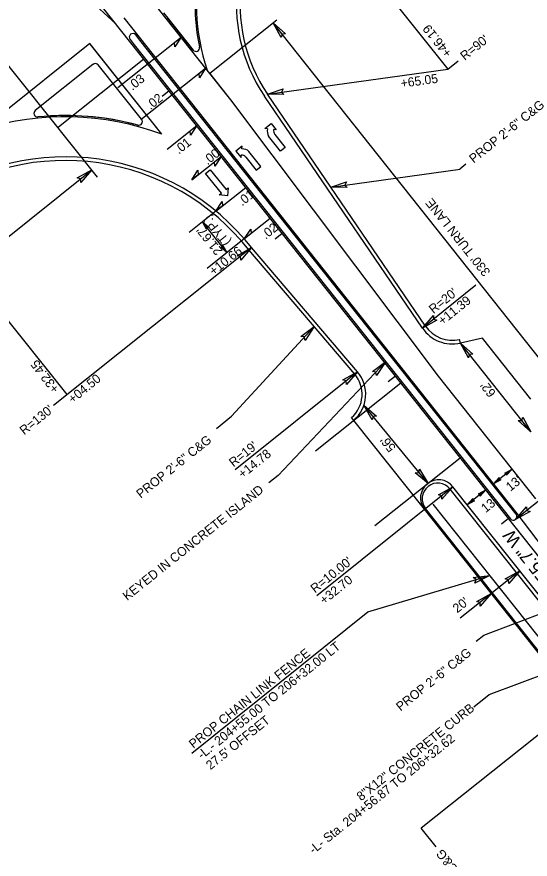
# Model space of a CAD drawing. Extents: x 472216 to 481979, y 489069 to 507339.
# Drawn here: x 473629 to 473911.3, y 505738.4 to 506201.2 of the extents above; entities that cross this region are included whole.
import ezdxf

# ---------------------------------------------------------------- set-up
doc = ezdxf.new("R2010")
doc.units = 0
for name, color, linetype in [('Old_Level_12', 7, 'Continuous'), ('Prop Drainage Structure Drop Inlet Grate 2 Narrow Slots and Sag Grates 840 24 CELL', 7, 'Continuous'), ('Prop Drainage Structure Drop Inlet Grate 2 Wide Slots and Sag Grates 840 22 Label', 7, 'Continuous'), ('Prop Drainage Structure Outlet Berm Ditch 850 10 CELL', 7, 'Continuous'), ('Prop Drainage Structure Pipe CSP 15in', 7, 'Continuous'), ('Prop Drainage Structure Pipe RCP 15in Class III Label', 7, 'Continuous'), ('Prop Drainage Structure Pipe RCP 24in Class III Label', 7, 'Continuous'), ('Prop Drainage Structure Pipe Side Drain 15in Label', 7, 'Continuous'), ('Prop Erosion Embankment Toe Protection Label', 7, 'Continuous'), ('Prop Erosion Rip Rap Single Stone CELL', 7, 'Continuous'), ('Prop Grid Mask', 7, 'Continuous'), ('Prop Horizontal Alignment Station Label', 7, 'Continuous'), ('Prop NEU Channel Block Detail CELL', 7, 'Continuous'), ('Sheet Block Revision CELL', 7, 'Continuous'), ('Sheet North Arrow Point CELL', 7, 'Continuous'), ('Sheet PE Seal Cell', 7, 'Continuous'), ('Sheet Plan And Profile CELL', 7, 'Continuous'), ('Sheet Plot Border Outside CELL', 7, 'Continuous')]:
    doc.layers.add(name, color=color, linetype=linetype)

msp = doc.modelspace()

# ---------------------------------------------------------------- linework, layer by layer
at = {"layer": 'Old_Level_12'}
msp.add_line((473683.68, 506197.16), (473500.48, 506366.9), dxfattribs=at)
at = {"layer": 'Prop Drainage Structure Drop Inlet Grate 2 Narrow Slots and Sag Grates 840 24 CELL'}
for p, q in [((473738.42, 506094.42), (473723.77, 506082.79)), ((473744.57, 506071.63), (473731.1, 506088.61)), ((473754.26, 506079.33), (473733.7, 506063.01))]:
    msp.add_line(p, q, dxfattribs=at)
for points in [[(473719.39, 506189.99), (473715.93, 506184.69), (473715.76, 506187.11)], [(473732.86, 506173.02), (473729.41, 506167.72), (473729.24, 506170.14)], [(473727.93, 506141.43), (473724.48, 506136.14), (473724.31, 506138.56)], [(473741.41, 506124.46), (473737.95, 506119.17), (473737.78, 506121.59)], [(473725.18, 506111.58), (473728.64, 506116.88), (473728.8, 506114.46)], [(473738.42, 506094.42), (473741.88, 506099.72), (473742.04, 506097.3)], [(473733.29, 506084.6), (473731.1, 506088.61), (473734.54, 506085.56), (473733.55, 506085.51)], [(473754.26, 506079.33), (473757.71, 506084.62), (473757.88, 506082.2)], [(473742.38, 506075.64), (473744.57, 506071.63), (473741.13, 506074.68), (473742.11, 506074.73)]]:
    msp.add_lwpolyline(points, close=True, dxfattribs=at)
at = {"layer": 'Prop Drainage Structure Drop Inlet Grate 2 Wide Slots and Sag Grates 840 22 Label'}
for p, q in [((473684.6, 506162.37), (473719.39, 506189.99)), ((473697.21, 506144.71), (473732.86, 506173.02)), ((473711.64, 506128.5), (473727.93, 506141.43)), ((473725.18, 506111.58), (473741.41, 506124.46)), ((473738.42, 506094.42), (473754.88, 506107.49)), ((473754.26, 506079.33), (473768.36, 506090.52))]:
    msp.add_line(p, q, dxfattribs=at)
at = {"layer": 'Prop Drainage Structure Outlet Berm Ditch 850 10 CELL'}
for points in [[(473774.33, 506189.91), (473769.94, 506197.92), (473776.82, 506191.83), (473774.86, 506191.73)], [(473775.92, 506158.44), (473766.79, 506158.74), (473775.53, 506161.57), (473774.61, 506159.83)], [(473662.28, 506112.7), (473670.29, 506117.08), (473664.2, 506110.2), (473664.11, 506112.17)], [(473810.74, 506107.38), (473801.61, 506107.67), (473810.36, 506110.5), (473809.44, 506108.76)], [(473750.16, 506069.98), (473758.09, 506074.51), (473752.12, 506067.51), (473751.99, 506069.48)], [(473860.02, 506034.61), (473852.02, 506030.19), (473858.09, 506037.1), (473858.19, 506035.13)], [(473785.2, 506025.56), (473792.44, 506031.13), (473787.49, 506023.39), (473787.09, 506025.32)], [(473877.3, 506013.93), (473872.92, 506021.95), (473879.8, 506015.85), (473877.83, 506015.76)], [(473824.53, 506006.29), (473831.84, 506011.77), (473826.79, 506004.09), (473826.41, 506006.03)], [(473808.33, 506001.77), (473816.33, 506006.19), (473810.26, 505999.28), (473810.16, 506001.25)], [(473824.38, 505979.82), (473819.86, 505987.76), (473826.85, 505981.78), (473824.88, 505981.65)], [(473907.18, 505981.29), (473911.57, 505973.27), (473904.68, 505979.37), (473906.65, 505979.46)], [(473850.5, 505952.7), (473855.13, 505944.83), (473848.06, 505950.71), (473850.03, 505950.86)], [(473897.35, 505950.57), (473901.35, 505952.76), (473898.31, 505949.32), (473898.26, 505950.31)], [(473895.18, 505946.87), (473891.18, 505944.68), (473894.22, 505948.12), (473894.27, 505947.14)], [(473860.84, 505938.65), (473868.84, 505943.06), (473862.77, 505936.16), (473862.67, 505938.12)], [(473882.88, 505939.05), (473886.88, 505941.24), (473883.84, 505937.8), (473883.79, 505938.78)], [(473880.71, 505935.35), (473876.7, 505933.15), (473879.75, 505936.59), (473879.8, 505935.61)], [(473911.21, 505929.5), (473903.22, 505925.09), (473909.28, 505931.99), (473909.38, 505930.03)], [(473897.56, 505892.38), (473905.51, 505896.87), (473899.51, 505889.91), (473899.39, 505891.87)], [(473880, 505893.16), (473889.07, 505894.26), (473880.86, 505890.13), (473881.5, 505891.99)], [(473881.89, 505879.95), (473889.85, 505884.44), (473883.85, 505877.47), (473883.73, 505879.44)]]:
    msp.add_lwpolyline(points, close=True, dxfattribs=at)
at = {"layer": 'Prop Drainage Structure Pipe RCP 15in Class III Label'}
for p, q in [((473733.69, 506171.98), (473701.63, 506212.36)), ((473904.13, 505928.37), (473687.98, 506200.59)), ((473669.18, 506186.48), (473609.96, 506139.25)), ((473708.69, 506136.73), (473669.18, 506186.48)), ((473708.68, 506136.73), (473669.61, 506185.94)), ((474036.62, 505752.65), (473904.13, 505928.37))]:
    msp.add_line(p, q, dxfattribs=at)
for centre, radius, start, end in [((473839.76, 506207.93), 112, 165.4515, 198.722), ((473655.65, 505994.28), 152, 69.5799, 107.4934)]:
    msp.add_arc(centre, radius, start, end, dxfattribs=at)
at = {"layer": 'Prop Drainage Structure Pipe RCP 24in Class III Label'}
for p, q in [((473852.02, 506030.19), (473765.14, 506157.61)), ((473758.09, 506074.51), (473754.58, 506078.62)), ((473816.33, 506006.19), (473758.09, 506074.51)), ((473885.11, 506024.68), (473872.92, 506021.95)), ((473911.73, 505991.16), (473885.11, 506024.68)), ((473853.17, 505930.62), (473814.27, 505979.46)), ((473978.79, 505804.57), (473868.84, 505943.06)), ((473963.13, 505792.14), (473853.17, 505930.62))]:
    msp.add_line(p, q, dxfattribs=at)
for centre, radius, start, end in [((473839.76, 506207.93), 90, 129.7563, 213.9898), ((473655.65, 505994.28), 130, 40.4477, 128.3913), ((473868.55, 506041.46), 20, 214.2895, 282.6333), ((473801.87, 505993.86), 19, 310.7369, 40.4477), ((473861, 505936.84), 10, 38.4488, 218.4488)]:
    msp.add_arc(centre, radius, start, end, dxfattribs=at)
at = {"layer": 'Prop Drainage Structure Pipe Side Drain 15in Label'}
for p, q in [((473765.45, 506139.78), (473768.85, 506142.58)), ((473766.93, 506139.62), (473765.45, 506139.78)), ((473768.85, 506142.58), (473771.71, 506139.11)), ((473774.09, 506127.41), (473767.46, 506135.62)), ((473771.71, 506139.11), (473770.23, 506139.27)), ((473770.91, 506136.6), (473776.66, 506129.48)), ((473752.99, 506130.09), (473749.54, 506127.37)), ((473749.54, 506127.37), (473752.32, 506123.83)), ((473752.83, 506128.62), (473752.99, 506130.09)), ((473763.26, 506119.04), (473756.63, 506127.25)), ((473776.66, 506129.48), (473774.09, 506127.41)), ((473752.32, 506123.83), (473752.48, 506125.31)), ((473754.95, 506124.09), (473760.69, 506116.97)), ((473732.74, 506115.16), (473735.31, 506117.23)), ((473735.31, 506117.23), (473744.1, 506106.34)), ((473760.69, 506116.97), (473763.26, 506119.04)), ((473741.53, 506104.26), (473732.74, 506115.16)), ((473744.1, 506106.34), (473745.27, 506107.28)), ((473745.27, 506107.28), (473744.83, 506102.88)), ((473740.36, 506103.32), (473741.53, 506104.26)), ((473744.83, 506102.88), (473740.36, 506103.32))]:
    msp.add_line(p, q, dxfattribs=at)
for centre, radius, start, end in [((473771.99, 506138.25), 5.25, 164.9163, 210.228), ((473773.44, 506138.65), 3.27, 169.2459, 218.9041), ((473753.1, 506123.38), 5.25, 47.5802, 92.8919), ((473752.4, 506122.05), 3.27, 38.9041, 88.5623)]:
    msp.add_arc(centre, radius, start, end, dxfattribs=at)
at = {"layer": 'Prop Erosion Embankment Toe Protection Label'}
for p, q in [((473746.66, 506155.64), (473733.69, 506171.98)), ((473746.66, 506155.64), (473735.07, 506170.23)), ((473860.89, 506003.73), (473746.66, 506155.64)), ((473914.41, 505936.32), (473860.89, 506003.73))]:
    msp.add_line(p, q, dxfattribs=at)
at = {"layer": 'Prop Erosion Rip Rap Single Stone CELL'}
msp.add_line((473967.97, 505794.88), (473857.91, 505933.5), dxfattribs=at)
at = {"layer": 'Prop Grid Mask'}
for p, q in [((473853.68, 506031.32), (473766.79, 506158.74)), ((473756.54, 506073.23), (473753.06, 506077.32)), ((473814.81, 506004.89), (473756.57, 506073.21)), ((473872.92, 506021.95), (473872.48, 506023.9)), ((473814.27, 505979.46), (473813.02, 505981.03)), ((473977.23, 505803.33), (473867.32, 505941.76))]:
    msp.add_line(p, q, dxfattribs=at)
for centre, radius, start, end in [((473839.76, 506207.93), 88, 129.7563, 213.9898), ((473655.65, 505994.28), 128, 40.4477, 128.3913), ((473868.55, 506041.46), 18, 214.2895, 282.6333), ((473801.87, 505993.86), 17, 310.9956, 40.4477), ((473860.53, 505936.37), 8.67, 38.4488, 218.4488)]:
    msp.add_arc(centre, radius, start, end, dxfattribs=at)
at = {"layer": 'Prop Horizontal Alignment Station Label'}
for p, q in [((473725.92, 506182.96), (473712.03, 506200.46)), ((473691.3, 506188.77), (473693.6, 506185.88)), ((473693.6, 506185.88), (473900.41, 505925.41)), ((473903.54, 505927.9), (473696.73, 506188.37)), ((473670.92, 506175.07), (473639.17, 506149.75)), ((473697.63, 506144.89), (473673.73, 506174.76))]:
    msp.add_line(p, q, dxfattribs=at)
for points in [[(473709.67, 506203.43), (473712.03, 506200.46), (473725.92, 506182.96)], [(473903.54, 505927.9), (473696.73, 506188.37), (473694.44, 506191.26)]]:
    msp.add_lwpolyline(points, dxfattribs=at)
for centre, radius, start, end in [((473839.76, 506207.93), 112.75, 176.0286, 191.9302), ((473839.76, 506207.93), 112.75, 176.0286, 191.9302), ((473692.87, 506190.02), 2, 38.4488, 218.4488), ((473727.49, 506184.21), 2, 218.4488, 11.9302), ((473727.49, 506184.21), 2, 218.4488, 11.9302), ((473672.17, 506173.51), 2, 38.6712, 128.5744), ((473640.42, 506148.19), 2, 128.5744, 275.7213), ((473655.85, 505994.21), 152.75, 74.9336, 95.7213), ((473655.85, 505994.21), 152.75, 74.9336, 93.717), ((473696.07, 506143.64), 2, 254.9336, 38.6712), ((473696.07, 506143.64), 2, 254.9336, 38.6712), ((473901.97, 505926.66), 2, 218.4488, 38.4488), ((473901.97, 505926.66), 2, 218.4488, 38.4488), ((473901.97, 505926.66), 2, 218.4488, 38.4488)]:
    msp.add_arc(centre, radius, start, end, dxfattribs=at)
at = {"layer": 'Prop NEU Channel Block Detail CELL'}
msp.add_line((473963.03, 505793.34), (473853.74, 505930.98), dxfattribs=at)
at = {"layer": 'Sheet Block Revision CELL'}
for p, q in [((473783.48, 506275.58), (473865.96, 506172.53)), ((473735.07, 506170.23), (473771.96, 506199.52)), ((473970.74, 505945.02), (473769.94, 506197.92)), ((473673.44, 506113.15), (473613.39, 506188.19)), ((473865.96, 506172.53), (473871.66, 506177.09)), ((473766.79, 506158.74), (473865.96, 506172.53)), ((473656.69, 505993.64), (473532.85, 506148.91)), ((473255.94, 505786.61), (473670.29, 506117.08)), ((473801.61, 506107.67), (473872.78, 506117.56)), ((473872.57, 506117.63), (473875.98, 506120.37)), ((473758.09, 506074.51), (473649.22, 505987.68)), ((473881.41, 506053.72), (473852.02, 506030.19)), ((473747.11, 505981.84), (473792.44, 506031.13)), ((473911.57, 505973.27), (473872.92, 506021.95)), ((473831.84, 506011.77), (473772.71, 505949.22)), ((473816.33, 506006.19), (473749.13, 505952.4)), ((473855.13, 505944.83), (473819.86, 505987.76)), ((473983.39, 505989.25), (473903.22, 505925.09)), ((473738.75, 505975.07), (473747.14, 505981.79)), ((473901.35, 505952.76), (473891.17, 505944.68)), ((473772.71, 505949.22), (473767.58, 505945.15)), ((473868.84, 505943.06), (473793.97, 505883.14)), ((473886.88, 505941.24), (473876.7, 505933.15)), ((473905.51, 505896.87), (473872.72, 505870.85)), ((473822.09, 505874.21), (473889.07, 505894.26)), ((473725.27, 505796.72), (473822.09, 505874.21)), ((473885.79, 505861.51), (473920.62, 505874.62)), ((473881.6, 505858.15), (473885.79, 505861.51)), ((473888.72, 505828.88), (473923.54, 505841.99)), ((473951.77, 505835.31), (473851.26, 505755.51)), ((473880.33, 505822.17), (473888.72, 505828.88)), ((473859.53, 505745.17), (473851.26, 505755.51))]:
    msp.add_line(p, q, dxfattribs=at)
at = {"layer": 'Sheet North Arrow Point CELL'}
msp.add_line((474109.5, 505660.85), (473657.57, 506230.05), dxfattribs=at)
at = {"layer": 'Sheet PE Seal Cell'}
for p, q in [((473712.8, 506160.49), (473708.89, 506157.38)), ((473774.98, 506082.17), (473771.07, 506079.06)), ((473837.17, 506003.85), (473833.25, 506000.75)), ((473899.35, 505925.54), (473895.43, 505922.43))]:
    msp.add_line(p, q, dxfattribs=at)
at = {"layer": 'Sheet Plot Border Outside CELL'}
for p, q in [((473651.87, 506140.75), (473698.86, 506178.05)), ((473793.2, 505962.73), (473840.19, 506000.04)), ((473825.81, 505921.66), (473872.8, 505958.97))]:
    msp.add_line(p, q, dxfattribs=at)

# ---------------------------------------------------------------- texts
at = {"layer": 'Prop Drainage Structure Drop Inlet Grate 2 Narrow Slots and Sag Grates 840 24 CELL'}
for s, rotation, p in [('.03', 38.4488, (473692.55, 506160.54)), ('.02', 38.4488, (473702.52, 506149.88)), ('.01', 38.4488, (473718.1, 506125.49)), ('.00', 38.4488, (473733.86, 506119.53)), ('.01', 38.4488, (473752.94, 506097.01)), ('(TYP.)', 128.4488, (473746.9, 506077.71)), ("21.67'", 128.4488, (473742.5, 506072.71)), ('.02', 38.4488, (473765.86, 506078.73)), ('+10.66', 38.4488, (473737.29, 506058.8))]:
    msp.add_text(s, height=5, rotation=rotation, dxfattribs=at).set_placement(p)
at = {"layer": 'Prop Drainage Structure Pipe CSP 15in'}
for s, rotation, p in [('+46.19', 128.6712, (473868.57, 506181.41)), ("R=90'", 38.6712, (473875.32, 506176.96)), ('+65.05', 7.9132, (473840.44, 506162.19)), ('PROP 2\'-6" C&G', 38.6712, (473880.21, 506120.52)), ("330' TURN LANE", 128.4488, (473889.68, 506061.13)), ("R=20'", 38.6712, (473858.07, 506037.84)), ('+11.39', 38.6712, (473863.1, 506031.56)), ('+32.45', 127.2513, (473652.68, 505996.84)), ('+04.50', 39.5094, (473659.81, 505988.48)), ("62'", 127.7688, (473892.72, 505994.61)), ("R=130'", 38.6712, (473633.07, 505971.24)), ('PROP 2\'-6" C&G', 38.6712, (473697.18, 505936.38)), ("56'", 128.6712, (473837.71, 505964.58)), ("R=19'", 38.6712, (473748.18, 505953.59)), ('+14.78', 38.6712, (473753.21, 505947.31)), ("13'", 38.4488, (473900.4, 505940.24)), ('KEYED IN CONCRETE ISLAND', 38.6712, (473689.76, 505880.21)), ("13'", 38.4488, (473886.79, 505928.47)), ("R=10.00'", 38.6712, (473793.01, 505884.33)), ('+32.70', 38.6712, (473798.04, 505878.05)), ("20'", 38.4488, (473871.19, 505873.41)), ('-L.- 204+55.00 TO 206+32.00 LT', 38.6712, (473730.82, 505793.1)), ('PROP CHAIN LINK FENCE', 38.6712, (473726.13, 505798.96)), ('PROP 2\'-6" C&G', 38.6712, (473840.03, 505819.46)), ('8"X12" CONCRETE CURB ', 38.7647, (473818.33, 505770.11)), ("27.5' OFFSET", 38.6712, (473735.5, 505787.25)), ('-L- Sta. 204+56.87 TO 206+32.62', 38.7647, (473792.16, 505740.97)), ('2\'-6" C&G', 128.6712, (473881.49, 505721.32))]:
    msp.add_text(s, height=5, rotation=rotation, dxfattribs=at).set_placement(p)
at = {"layer": 'Sheet Plan And Profile CELL'}
msp.add_text('N 38%%d 26\' 55.7" W', height=7, rotation=128.4488, dxfattribs=at).set_placement((473947.27, 505862.4))

doc.saveas('drawing.dxf')
